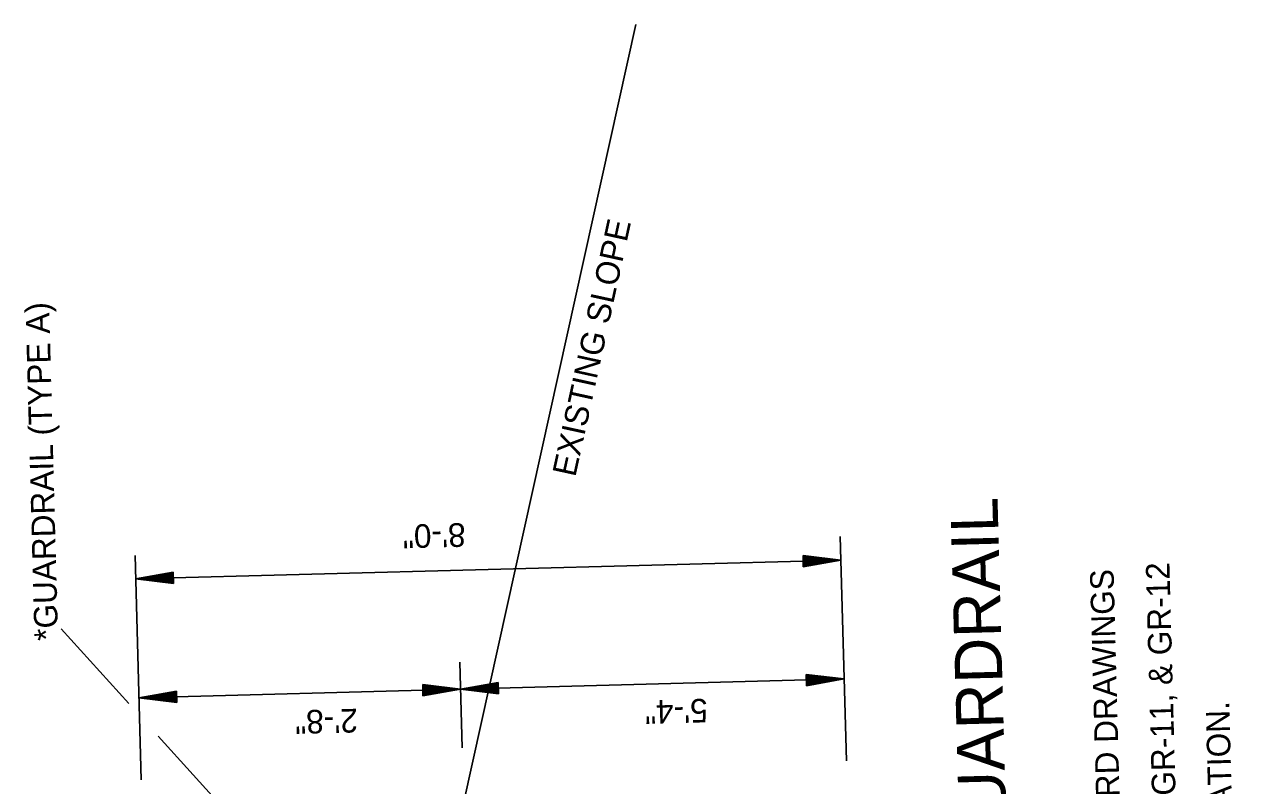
# Model space of a CAD drawing. Extents: x 1926836 to 1933254, y 596317 to 604524.
# Drawn here: x 1932899.1 to 1933208.5, y 601447.9 to 601641.3 of the extents above; entities that cross this region are included whole.
import ezdxf

# ---------------------------------------------------------------- set-up
doc = ezdxf.new("R2010")
doc.units = 0
doc.layers.add('Default', color=7, linetype='Continuous')

msp = doc.modelspace()

# ---------------------------------------------------------------- linework, layer by layer
at = {"layer": 'Default'}
for p, q in [((1933010.64, 601443.83), (1933054.39, 601641.34)), ((1933106.29, 601511.21), (1933107.82, 601454.18)), ((1932927.18, 601506.4), (1932928.71, 601449.37)), ((1933106.45, 601505.23), (1932927.34, 601500.42)), ((1933096.81, 601506.41), (1933106.45, 601505.23)), ((1933096.81, 601506.41), (1933096.89, 601503.53)), ((1933096.82, 601506.17), (1933104.84, 601505.19)), ((1933096.82, 601505.93), (1933103.19, 601505.14)), ((1933096.83, 601505.69), (1933101.6, 601505.1)), ((1933096.84, 601505.44), (1933099.97, 601505.06)), ((1933096.84, 601505.2), (1933098.37, 601505.01)), ((1933096.86, 601504.5), (1933099.97, 601505.06)), ((1933096.86, 601504.75), (1933098.37, 601505.01)), ((1933096.87, 601504.26), (1933101.6, 601505.1)), ((1933096.88, 601503.77), (1933104.84, 601505.19)), ((1933096.88, 601504.02), (1933103.19, 601505.14)), ((1933096.89, 601503.53), (1933106.45, 601505.23)), ((1932936.9, 601502.12), (1932927.34, 601500.42)), ((1932936.91, 601501.88), (1932928.95, 601500.46)), ((1932936.98, 601499.24), (1932936.9, 601502.12)), ((1932936.98, 601499.24), (1932927.34, 601500.42)), ((1932936.97, 601499.48), (1932928.95, 601500.46)), ((1932936.91, 601501.63), (1932930.6, 601500.51)), ((1932936.96, 601499.72), (1932930.6, 601500.51)), ((1932936.92, 601501.39), (1932932.19, 601500.55)), ((1932936.96, 601499.96), (1932932.19, 601500.55)), ((1932936.93, 601501.15), (1932933.82, 601500.6)), ((1932936.95, 601500.21), (1932933.82, 601500.6)), ((1932936.93, 601500.9), (1932935.42, 601500.64)), ((1932936.95, 601500.45), (1932935.42, 601500.64)), ((1932925.62, 601468.78), (1932908.43, 601487.78)), ((1933009.68, 601479.3), (1933010.27, 601457.54)), ((1933009.87, 601472.39), (1933107.26, 601475.01)), ((1933019.43, 601474.09), (1933009.87, 601472.39)), ((1933019.43, 601473.85), (1933011.47, 601472.43)), ((1933019.5, 601471.21), (1933019.43, 601474.09)), ((1933097.62, 601476.19), (1933107.26, 601475.01)), ((1933097.62, 601476.19), (1933097.7, 601473.31)), ((1933097.63, 601475.95), (1933105.66, 601474.96)), ((1933097.64, 601475.7), (1933104, 601474.92)), ((1933097.64, 601475.46), (1933102.41, 601474.88)), ((1933097.65, 601475.21), (1933100.78, 601474.83)), ((1933097.66, 601474.97), (1933099.18, 601474.79)), ((1933097.67, 601474.28), (1933100.78, 601474.83)), ((1933097.67, 601474.52), (1933099.18, 601474.79)), ((1933097.68, 601474.03), (1933102.41, 601474.88)), ((1933097.69, 601473.55), (1933105.66, 601474.96)), ((1933097.69, 601473.79), (1933104, 601474.92)), ((1933097.7, 601473.31), (1933107.26, 601475.01)), ((1933009.87, 601472.39), (1932928.15, 601470.2)), ((1932937.71, 601471.9), (1932928.15, 601470.2)), ((1932937.72, 601471.66), (1932929.76, 601470.24)), ((1932937.72, 601471.41), (1932931.41, 601470.29)), ((1932937.73, 601471.17), (1932933, 601470.33)), ((1932937.74, 601470.93), (1932934.63, 601470.37)), ((1932937.79, 601469.02), (1932937.71, 601471.9)), ((1933000.23, 601473.57), (1933009.87, 601472.39)), ((1933000.23, 601473.57), (1933000.31, 601470.69)), ((1933000.24, 601473.33), (1933008.27, 601472.35)), ((1933000.25, 601473.09), (1933006.62, 601472.3)), ((1933000.25, 601472.85), (1933005.02, 601472.26)), ((1933000.26, 601472.6), (1933003.39, 601472.22)), ((1933000.27, 601472.36), (1933001.79, 601472.17)), ((1933000.28, 601471.66), (1933003.39, 601472.22)), ((1933000.28, 601471.91), (1933001.79, 601472.17)), ((1933000.29, 601471.42), (1933005.02, 601472.26)), ((1933000.3, 601470.93), (1933008.27, 601472.35)), ((1933000.3, 601471.18), (1933006.62, 601472.3)), ((1933000.31, 601470.69), (1933009.87, 601472.39)), ((1933019.5, 601471.21), (1933009.87, 601472.39)), ((1933019.5, 601471.45), (1933011.47, 601472.43)), ((1933019.44, 601473.6), (1933013.12, 601472.48)), ((1933019.49, 601471.69), (1933013.12, 601472.48)), ((1933019.45, 601473.36), (1933014.72, 601472.52)), ((1933019.48, 601471.93), (1933014.72, 601472.52)), ((1933019.45, 601473.12), (1933016.35, 601472.57)), ((1933019.48, 601472.18), (1933016.35, 601472.57)), ((1933019.46, 601472.87), (1933017.95, 601472.61)), ((1933019.47, 601472.42), (1933017.95, 601472.61)), ((1932937.79, 601469.02), (1932928.15, 601470.2)), ((1932937.78, 601469.26), (1932929.76, 601470.24)), ((1932937.78, 601469.5), (1932931.41, 601470.29)), ((1932937.77, 601469.74), (1932933, 601470.33)), ((1932937.76, 601469.99), (1932934.63, 601470.37)), ((1932937.74, 601470.68), (1932936.23, 601470.42)), ((1932937.76, 601470.23), (1932936.23, 601470.42)), ((1932954.31, 601437.08), (1932933.09, 601460.52))]:
    msp.add_line(p, q, dxfattribs=at)

# ---------------------------------------------------------------- texts
for s, height, rotation, p in [('EXISTING SLOPE', 6, 77.6663, (1933038.98, 601526.15)), ('*GUARDRAIL (TYPE A)', 6, 91.5377, (1932907.66, 601484.8)), ('SECTION DETAIL FOR GUARDRAIL', 12, 91.5377, (1933153.4, 601253.02)), ('8\'-0"', 6, 181.5377, (1933011.04, 601514.64)), ('NOTE:  REFER TO STANDARD DRAWINGS ', 6, 91.5377, (1933180.02, 601340.79)), ('GR-8, GR-9, GR-9A, GR-10, GR-11, & GR-12', 6, 91.5377, (1933194.24, 601341.17)), ('5\'-4"', 6, 181.5377, (1933072.53, 601470.01)), ('FOR ADDITIONAL INFORMATION.', 6, 91.5377, (1933208.47, 601341.55)), ('2\'-8"', 6, 181.5377, (1932983.69, 601467.46))]:
    msp.add_text(s, height=height, rotation=rotation, dxfattribs=at).set_placement(p)

doc.saveas('drawing.dxf')
